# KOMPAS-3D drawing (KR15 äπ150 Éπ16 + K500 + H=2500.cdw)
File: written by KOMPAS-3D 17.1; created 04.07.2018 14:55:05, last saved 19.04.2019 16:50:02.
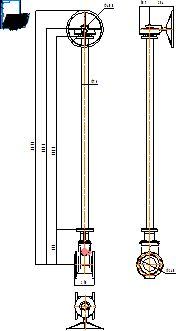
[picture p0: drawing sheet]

Sheet 1: A4, portrait

Title block, sheet 1: name: KR15 Ду150 Ру16 + / K500 + H=2500; material: Внимание! Данный продукт является объектом авторского права ООО «Торговый Дом АДЛ». / Запрещается изменение, копирование, распространение / (в том числе путем копирования на другие сайты и ресурсы в Интернете) / или любое иное использование информации и объектов без предварительного / согласия правообладателя (ООО «Торговый Дом АДЛ»).; mass: 36,7; sheets: 1; organisation: ООО "Торговый дом АДЛ"; sheet format: A4; stored path: \\adlc.lan\data\АДЛ_ПКД\3D-модели\ADL production\Клиновые задвижки серии KR ГРАНАР\Клиновые задвижки KR15 со стационарным удлинением\KOMPAS 2D\KR15 Ду150 Ру16 + K500 + H=2500.cdw

Views: Проекционный вид 6, Спереди 9, Проекционный вид 10
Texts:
  kka
  adl
Dimensions and other numbers on the sheet: 2500; 2045; 2696; 400; 76; 370; 210; 109; 240; 254; 1:1; 1; 36,7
